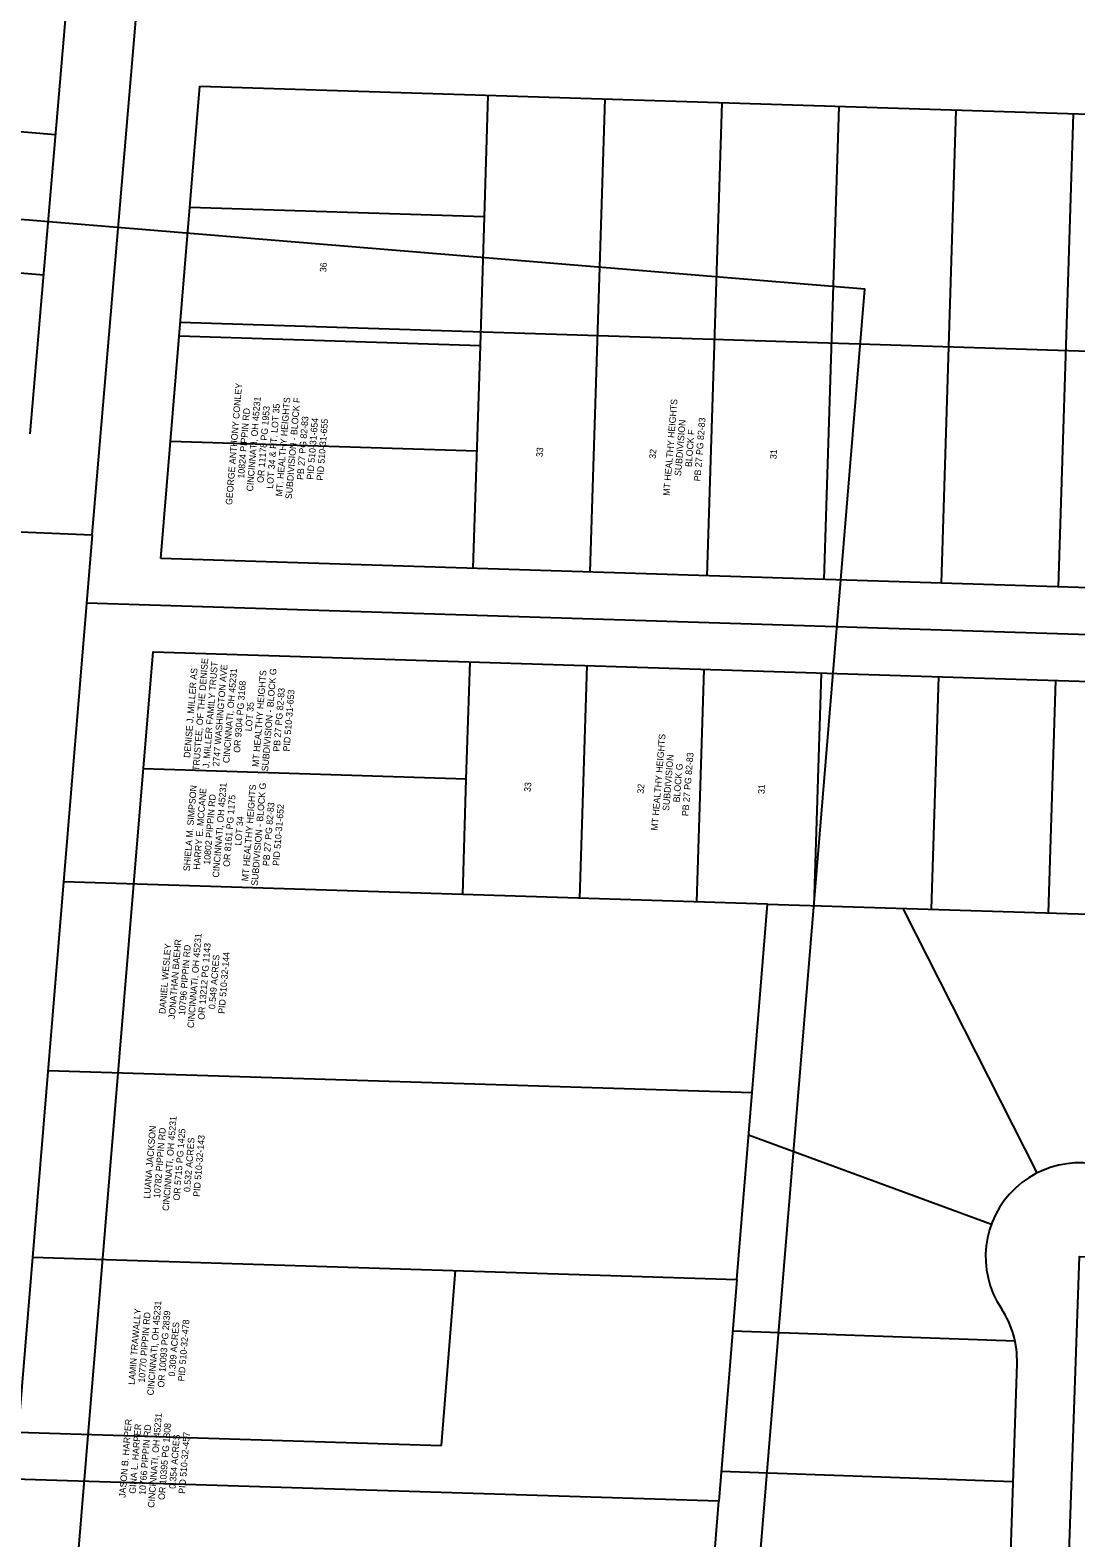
# Model space of a CAD drawing. Extents: x 1379776 to 1382941, y 467490 to 471592.
# Drawn here: x 1381596 to 1382042, y 469835 to 470478 of the extents above; entities that cross this region are included whole.
import ezdxf

# ---------------------------------------------------------------- set-up
doc = ezdxf.new("R2010")
doc.units = 0
for name, color, linetype in [('DR_X_Text', 7, 'Continuous'), ('PV_P_Drive', 7, 'Continuous'), ('PV_X_Driveway', 7, 'Continuous'), ('RC_X_Text', 7, 'Continuous'), ('RD_X_Wall', 7, 'Continuous'), ('SH_Named_Boundary', 7, 'Continuous'), ('SV_X_Break_Lines', 7, 'Continuous')]:
    doc.layers.add(name, color=color, linetype=linetype)

msp = doc.modelspace()

# ---------------------------------------------------------------- linework, layer by layer
at = {"layer": 'DR_X_Text'}
msp.add_line((1381620.01, 470233.64), (1382933.73, 470192.12), dxfattribs=at)
msp.add_lwpolyline([(1382016.8, 469180.11), (1382043.72, 469954.66), (1382306.88, 469945.51)], dxfattribs=at)
at = {"layer": 'PV_P_Drive'}
for p, q in [((1381487.22, 470443.68), (1381606.79, 470433.53)), ((1381482.15, 470383.89), (1381601.72, 470373.74)), ((1381787.94, 470343.39), (1381659.52, 470347.45)), ((1381787.94, 470343.39), (1381784.94, 470248.44)), ((1380559.29, 470305.26), (1381622.42, 470262.79)), ((1381622.42, 470262.79), (1381580.75, 469758.51)), ((1381782.09, 470158.48), (1381783.67, 470208.46)), ((1381782.09, 470158.48), (1381644.26, 470162.84)), ((1381780.54, 470109.22), (1381782.09, 470158.48)), ((1381910.57, 470105.11), (1381610.17, 470114.6)), ((1381904.03, 470024.65), (1381910.57, 470105.11)), ((1381910.57, 470105.11), (1382929.96, 470072.89)), ((1381603.52, 470034.14), (1381904.03, 470024.65)), ((1381897.55, 469944.91), (1381904.03, 470024.65)), ((1381596.93, 469954.41), (1381897.55, 469944.91)), ((1381771.53, 469873.97), (1381777.53, 469948.7)), ((1381897.55, 469944.91), (1381889.85, 469850.22)), ((1381590.76, 469879.68), (1381771.53, 469873.97)), ((1381889.85, 469850.22), (1381589.11, 469859.72)), ((1381880.85, 469739.58), (1381889.85, 469850.22))]:
    msp.add_line(p, q, dxfattribs=at)
msp.add_lwpolyline([(1381622.42, 470262.79), (1381734.98, 471589.3), (1381584.7, 471592.38), (1381564.18, 471350.58), (1381599.47, 471352.44), (1381589.32, 471232.87), (1381661.56, 471226.74)], dxfattribs=at)
at = {"layer": 'PV_X_Driveway'}
msp.add_line((1381609.99, 469748.14), (1381640.2, 470113.65), dxfattribs=at)
at = {"layer": 'RD_X_Wall'}
for p, q in [((1381595.96, 470305.82), (1381704.92, 471589.92)), ((1381651.68, 470252.65), (1381668.34, 470454.22)), ((1381668.34, 470454.22), (1382940.74, 470414.01)), ((1382934.36, 470212.11), (1381651.68, 470252.65)), ((1382017.11, 469908.92), (1382004.68, 469551.25))]:
    msp.add_line(p, q, dxfattribs=at)
msp.add_lwpolyline([(1381640.2, 470113.65), (1381648.38, 470212.73), (1382933.1, 470172.13), (1382929.96, 470072.89)], dxfattribs=at)
for centre, start, end in [((1382043.72, 469954.66), 52.35034, 213.66851), ((1381977.14, 469910.31), 358.00942, 33.66851)]:
    msp.add_arc(centre, 40, start, end, dxfattribs=at)
at = {"layer": 'SH_Named_Boundary'}
msp.add_lwpolyline([(1381019.66, 469039.84), (1381836.87, 468972.31), (1381848.4, 469111.83), (1381859.93, 469251.36), (1381871.46, 469390.88), (1381882.99, 469530.4), (1381894.52, 469669.93), (1381906.05, 469809.45), (1381917.58, 469948.98), (1381929.11, 470088.5), (1381940.64, 470228.03), (1381952.16, 470367.55), (1381134.95, 470435.08), (1381123.42, 470295.56), (1381111.89, 470156.03), (1381100.36, 470016.51), (1381088.83, 469876.98), (1381077.3, 469737.46), (1381065.77, 469597.93), (1381054.24, 469458.41), (1381042.71, 469318.88), (1381031.19, 469179.36)], close=True, dxfattribs=at)
at = {"layer": 'SV_X_Break_Lines'}
for p, q in [((1381791.32, 470450.34), (1381789.68, 470398.51)), ((1381834.91, 470246.86), (1381841.29, 470448.76)), ((1381884.89, 470245.28), (1381891.27, 470447.18)), ((1381934.86, 470243.7), (1381941.24, 470445.6)), ((1381984.84, 470242.12), (1381991.22, 470444.02)), ((1382034.81, 470240.54), (1382041.19, 470442.44)), ((1381789.68, 470398.51), (1381664.06, 470402.48)), ((1381789.68, 470398.51), (1381787.94, 470343.39)), ((1381660.01, 470353.43), (1382937.55, 470313.06)), ((1381786.52, 470298.46), (1381655.81, 470302.59)), ((1381830.51, 470107.64), (1381833.65, 470206.88)), ((1381880.49, 470106.06), (1381883.62, 470205.3)), ((1381933.6, 470203.72), (1381930.46, 470104.48)), ((1381983.57, 470202.14), (1381980.44, 470102.9)), ((1382033.55, 470200.56), (1382030.41, 470101.32)), ((1381968.38, 470103.28), (1382025.63, 469990.34)), ((1381902.56, 470006.57), (1382006.18, 469968.47)), ((1382016.27, 469918.57), (1381895.75, 469922.76)), ((1382015.36, 469858.57), (1381890.88, 469862.89))]:
    msp.add_line(p, q, dxfattribs=at)

# ---------------------------------------------------------------- texts
at = {"layer": 'RC_X_Text'}
for s, p in [('36', (1381722.3, 470374.74)), ('GEORGE ANTHONY CONLEY', (1381682.14, 470275.39)), ('CINCINNATI, OH 45231', (1381691.04, 470281.16)), ('MT. HEALTHY HEIGHTS', (1381703.51, 470279.03)), ('SUBDIVISION - BLOCK F', (1381707.63, 470277.87)), ('MT HEALTHY HEIGHTS', (1381868.82, 470279.32)), ('10824 PIPPIN RD', (1381687.28, 470286.65)), ('OR 11178 PG 1953', (1381695.56, 470284.81)), ('LOT 34 & PT. LOT 35', (1381699.57, 470282.31)), ('PB 27 PG 82-83', (1381712.52, 470286.07)), ('PID 510-31-654', (1381716.74, 470286.18)), ('PID 510-31-655', (1381720.93, 470285.78)), ('SUBDIVISION', (1381873.73, 470287.73)), ('BLOCK F', (1381878.26, 470291.57)), ('PB 27 PG 82-83', (1381881.97, 470285.47)), ('33', (1381814.62, 470295.8)), ('32', (1381862.88, 470295.08)), ('31', (1381914.41, 470294.94)), ('DENISE J. MILLER AS', (1381664.25, 470167.41)), ('TRUSTEE, OF THE DENISE', (1381668.01, 470161.86)), ('J. MILLER FAMILY TRUST', (1381672.33, 470163.14)), ('2747 WASHINGTON AVE', (1381676.59, 470163.76)), ('CINCINNATI, OH 45231', (1381680.92, 470165.18)), ('MT HEALTHY HEIGHTS', (1381693.44, 470163.58)), ('SUBDIVISION - BLOCK G', (1381697.49, 470161.68)), ('OR 9304 PG 3168', (1381685.51, 470169.61)), ('PB 27 PG 82-83', (1381702.4, 470170.08)), ('LOT 35', (1381690.48, 470178.78)), ('PID 510-31-653', (1381706.62, 470170.17)), ('MT HEALTHY HEIGHTS', (1381863.71, 470136.39)), ('SUBDIVISION', (1381868.62, 470144.81)), ('PB 27 PG 82-83', (1381876.86, 470142.55)), ('BLOCK G', (1381873.13, 470148.44)), ('SHIELA M. SIMPSON', (1381664.07, 470119.06)), ('HARRY E. MCCANE', (1381668.33, 470119.7)), ('CINCINNATI, OH 45231', (1381676.49, 470116.36)), ('MT HEALTHY HEIGHTS', (1381689, 470114.76)), ('SUBDIVISION - BLOCK G', (1381693.05, 470112.86)), ('33', (1381809.51, 470152.88)), ('32', (1381857.77, 470152.16)), ('31', (1381909.3, 470152.02)), ('10802 PIPPIN RD', (1381672.72, 470121.84)), ('OR 8161 PG 1175', (1381681.08, 470120.92)), ('PB 27 PG 82-83', (1381697.96, 470121.26)), ('PID 510-31-652', (1381702.18, 470121.34)), ('LOT 34', (1381686.04, 470130.02)), ('DANIEL WESLEY', (1381653.65, 470058.1)), ('JONATHAN BAEHR', (1381657.69, 470056)), ('CINCINNATI, OH 45231', (1381665.8, 470052.12)), ('OR 13212 PG 1143', (1381670.3, 470055.63)), ('10796 PIPPIN RD', (1381662.03, 470057.6)), ('0.549 ACRES', (1381674.89, 470060.18)), ('PID 510-32-144', (1381678.94, 470058.18)), ('CINCINNATI, OH 45231', (1381655.13, 469974.05)), ('LUANA JACKSON', (1381647.14, 469979.33)), ('10782 PIPPIN RD', (1381651.37, 469979.54)), ('OR 5715 PG 1425', (1381659.71, 469978.47)), ('0.532 ACRES', (1381664.23, 469982.12)), ('PID 510-32-143', (1381668.27, 469980.08)), ('CINCINNATI, OH 45231', (1381648.62, 469895.3)), ('LAMIN TRAWALLY', (1381640.57, 469899.85)), ('10770 PIPPIN RD', (1381644.86, 469900.78)), ('OR 10093 PG 2839', (1381653.12, 469898.67)), ('PID 510-32-478', (1381661.76, 469901.31)), ('0.309 ACRES', (1381657.72, 469903.36)), ('JASON B. HARPER', (1381636.59, 469851.65)), ('GINA L. HARPER', (1381640.94, 469853.33)), ('10766 PIPPIN RD', (1381645.11, 469852.84)), ('CINCINNATI, OH 45231', (1381648.87, 469847.35)), ('OR 10395 PG 1808', (1381653.37, 469850.7)), ('0.354 ACRES', (1381657.97, 469855.42)), ('PID 510-32-457', (1381662.01, 469853.31))]:
    msp.add_text(s, height=2.8, rotation=85.27618, dxfattribs=at).set_placement(p)

doc.saveas('drawing.dxf')
